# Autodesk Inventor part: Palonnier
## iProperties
Author: Philippe
Created: 2002-01
Part Number: Palonnier
Material: Par défaut
Document SubType Name: Modélisation
Designer: Philippe
Control State: 0
Master: False
Checked Out: False
PropertySet Name: Design Tracking Control
Shininess: 21.0
Angle Display Precision: 2
Document Length Units: 11269
Document Angle Units: 11283
Document Time Units: 11279
Document Mass Units: 11290
Document Length Units Precision: 3
Document Angle Units Precision: 2
Compacted: False
PropertySet Name: _Private Model Information
Density: 0.0
Volumn: 0.0
Area: 0.0
PropertySet Name: Model Information
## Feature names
1. Extrusion1
2. Extrusion2
3. Perçage1 [Hole]
4. Réseau circulaire1 [Circular Pattern]
5. Extrusion3
6. Extrusion4
7. Réseau circulaire2 [Circular Pattern]
8. Perçage2 [Hole]
